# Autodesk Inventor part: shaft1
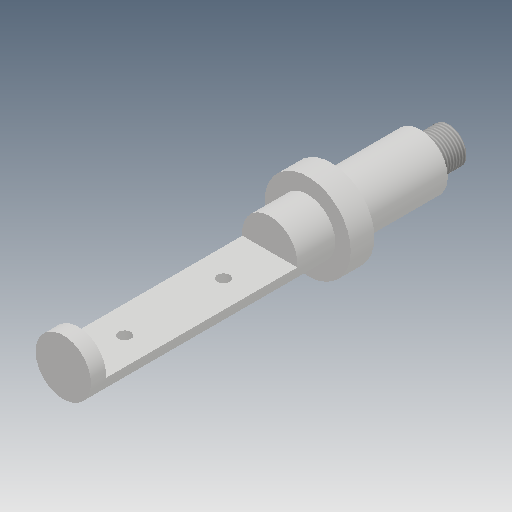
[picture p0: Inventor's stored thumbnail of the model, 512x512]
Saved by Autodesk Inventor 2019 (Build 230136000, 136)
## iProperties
Created: 2016-07
Part Number: shaft1
Material: Generic
Document SubType Name: Modeling
Designer: Sandeep
Density: 1 g/cm^3
Appearance: Default
Author: Sandeep
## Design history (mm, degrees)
sketch "Sketch1"
  geometry: L1 (-125.556, 0)-(92.286, 0); L2 (0, 18)-(28.9, 18); L3 (28.9, 18)-(28.9, 28); L4 (28.9, 28)-(118.7, 28); L5 (118.7, 28)-(118.7, 43.6); L6 (118.7, 43.6)-(142.7, 43.6); L7 (142.7, 43.6)-(142.7, 28); L8 (142.7, 28)-(389.8, 28); L9 (389.8, 28)-(389.8, 0); L10 (0, 18)-(0, 0); L11 (0, 0)-(389.8, 0)
  constraints: 22 end point, 7 perpendicular, 3 point on line, 2 horizontal, 1 collinear
  dimensions: "d0" = 36 diameter of L2 L1; "d1" = 56 diameter of L4 L1; "d2" = 87.2 diameter of L6 L1; "d3" = 28.9 distance between parallel lines of L3 L10; "d5" = 247.1 distance between parallel lines of L9 L7; "d6" = 24 distance between parallel lines of L5 L7; "d7" = 89.8 distance between parallel lines of L3 L5
revolve "Revolution1" sketch "Sketch1" stored, may be unused: angle "d8" = 90 deg
sketch "Sketch5"
  geometry: L1 (-142.7, 28)-(-389.8, 28) reference; L2 (-180.9, 28)-(-374.7, 28); L3 (-374.7, 28)-(-374.7, -3.1); L4 (-374.7, -3.1)-(-180.9, -3.1); L5 (-180.9, -3.1)-(-180.9, 28); L6 (-389.8, 28)-(-389.8, -28) reference; 1 further point
  constraints: 8 end point, 2 parallel, 1 horizontal, 1 perpendicular, 1 point on line
  dimensions: "d18" = 15.1 distance between parallel lines of L6 L3; "d19" = 193.8 distance between parallel lines of L5 L3; "d20" = 24.9 distance from line of L6.end L4
extrude "Extrusion3" cut sketch "Sketch5" stored distance "d21" = 62.5; taper "d22" = 0 deg
sketch "Sketch6"
  geometry: L1 (0, 0.172)-(0, -55.828) reference; L2 (208.9, -55.828)-(208.9, 0.172) reference; L3 (208.9, -27.828)-(-12.149, -27.828); C1 r 6.25 at (146.9, -27.828); C2 r 6.25 at (46.9, -27.828); 3 further points
  constraints: 2 centre point, 2 end point, 2 point on line, 1 equal radius, 1 horizontal, 1 midpoint
  dimensions: "d23" = 100 distance of C1.centre C2.centre; "d24" = 12.5 diameter of C2; "d25" = 46.9 distance from line of L1 C2.centre
extrude "Extrusion4" cut sketch "Sketch6" distance "d26" = 62.5; taper "d27" = 0 deg
thread "Thread1" dims "d28" = 10, "d29" = 0
sketch "Sketch9"
  geometry: L1 (-8, -26.833)-(-8, -22); L2 (-8, -22)-(8, -22); L3 (8, -22)-(8, -26.833); L4 (0, 0)-(0, -22.852); A1 r 28 centre (0, 0) between (8, -26.833) and (-8, -26.833) reference; 2 further points
  constraints: 8 end point, 3 point on circle, 1 parallel, 1 vertical, 1 other
  dimensions: "d34" = 16 distance between parallel lines of L1 L3; "d35" = 50 dimension on A1 L2
extrude "Extrusion5" cut sketch "Sketch9" distance "d36" = 66; taper "d37" = 0 deg
body "Solid1"
